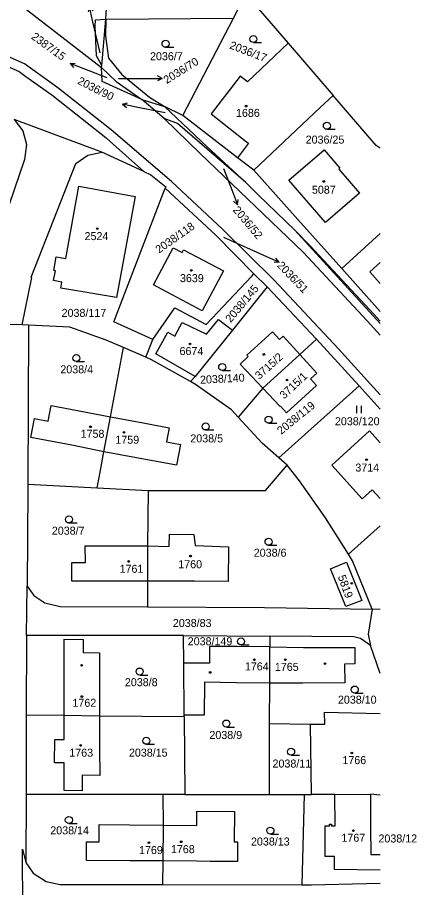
# Model space of a CAD drawing. Extents: x -667048 to -665920, y -1108425 to -1107247.
# Drawn here: x -666004.4 to -665919.6, y -1107911.7 to -1107726.9 of the extents above; entities that cross this region are included whole.
import ezdxf

# ---------------------------------------------------------------- set-up
doc = ezdxf.new("R2010")
doc.units = 0
for name, color, linetype in [('Default', 7, 'Continuous'), ('Hranice parcel', 7, 'Continuous'), ('Parcelní čísla', 7, 'Continuous'), ('Pop_ PČ_ popisy', 7, 'Continuous'), ('Značky budov', 7, 'Continuous'), ('Značky kultur', 7, 'Continuous')]:
    doc.layers.add(name, color=color, linetype=linetype)

# ---------------------------------------------------------------- blocks, each defined once
blk = doc.blocks.new('3.041')
at = {"layer": 'Default'}
blk.add_line((8, 0), (1758, 0), dxfattribs=at)
blk.add_circle((8, 750), 750, dxfattribs=at)
blk = doc.blocks.new('4.021')
at = {"layer": 'Default'}
blk.add_circle((-7, 1), 175, dxfattribs=at)
blk = doc.blocks.new('10291')
at = {"layer": 'Default'}
for p, q in [((0, 3001), (-500, 2001)), ((0, 1), (0, 3001)), ((0, 3001), (500, 2001))]:
    blk.add_line(p, q, dxfattribs=at)
blk = doc.blocks.new('3.061')
at = {"layer": 'Default'}
for p, q in [((-511, -1), (-511, 1499)), ((489, -1), (489, 1499))]:
    blk.add_line(p, q, dxfattribs=at)

msp = doc.modelspace()

# ---------------------------------------------------------------- linework, layer by layer
at = {"layer": 'Hranice parcel'}
for points in [[(-665985.61, -1107727.21), (-665985.17, -1107720.14)], [(-665958.54, -1107727.02), (-665955.87, -1107721.88)], [(-665955.87, -1107721.88), (-665946.87, -1107732.34)], [(-666004.06, -1107724), (-665986.55, -1107737.54)], [(-666025.82, -1107726.88), (-666018.01, -1107732.17), (-666004.04, -1107738.39)], [(-665987.87, -1107728.74), (-665987.84, -1107727.35), (-665985.61, -1107727.21)], [(-665986.51, -1107737.08), (-665985.61, -1107727.21)], [(-665985.61, -1107727.21), (-665985.72, -1107730.82), (-665985.06, -1107735.53), (-665982.21, -1107738.96), (-665976.38, -1107743.84)], [(-665985.61, -1107727.21), (-665958.54, -1107727.02)], [(-665969.29, -1107747.69), (-665958.54, -1107727.02)], [(-665987.64, -1107735), (-665987.87, -1107728.74)], [(-665927.32, -1107807.05), (-665936.22, -1107797.25), (-665949.88, -1107782.67), (-665960.81, -1107771.82), (-665971.71, -1107761.69), (-665984.47, -1107750.77), (-665995.85, -1107741.81), (-666002.94, -1107736.71), (-666017.32, -1107730.34)], [(-665946.87, -1107732.34), (-665955.55, -1107740.57), (-665957.08, -1107739.36), (-665963.26, -1107747.35), (-665955.73, -1107753.31), (-665955.35, -1107753.61), (-665957.62, -1107756.67)], [(-665946.87, -1107732.34), (-665937.35, -1107743.42)], [(-665986.51, -1107737.08), (-665987.64, -1107735)], [(-665986.55, -1107737.54), (-665986.51, -1107737.08)], [(-666004.04, -1107738.39), (-666002.62, -1107739.4), (-665997.13, -1107743.32)], [(-665986.55, -1107737.54), (-665983.44, -1107740.5)], [(-665986.44, -1107740.46), (-665986.55, -1107737.54)], [(-665977.97, -1107744.27), (-665986.44, -1107740.46)], [(-665983.44, -1107740.5), (-665977.97, -1107744.27)], [(-665997.13, -1107743.32), (-665985.59, -1107752.46)], [(-665977.97, -1107744.27), (-665973.15, -1107745.82)], [(-665973.21, -1107748.36), (-665977.97, -1107744.27)], [(-665976.38, -1107743.84), (-665973.15, -1107745.82)], [(-665937.35, -1107743.42), (-665940.06, -1107745.99), (-665954.17, -1107759.33)], [(-665927.32, -1107754.65), (-665928.17, -1107754.07), (-665937.35, -1107743.42)], [(-665973.15, -1107745.82), (-665964.12, -1107754.36), (-665955.88, -1107761.95)], [(-665969.29, -1107747.69), (-665973.15, -1107745.82)], [(-666005.07, -1107748.54), (-666003.24, -1107750.99), (-666002.46, -1107753.88), (-666002.9, -1107757.03), (-666007.26, -1107769.91)], [(-665986.51, -1107755.5), (-666005.07, -1107748.54)], [(-665955.88, -1107761.95), (-665970.4, -1107749.41), (-665973.21, -1107748.36)], [(-665973.21, -1107748.36), (-665965.59, -1107755.78)], [(-665957.62, -1107756.67), (-665969.29, -1107747.69)], [(-665985.59, -1107752.46), (-665984.69, -1107753.2), (-665977.55, -1107759.63)], [(-666001.49, -1107782.06), (-665992.01, -1107757.88), (-665989.42, -1107756.16), (-665986.51, -1107755.5)], [(-665977.55, -1107759.63), (-665986.51, -1107755.5)], [(-665965.59, -1107755.78), (-665943.74, -1107776.75), (-665930.08, -1107791.32), (-665927.32, -1107794.36)], [(-665936.13, -1107759.08), (-665931.75, -1107764.2), (-665938.99, -1107770.45), (-665946.72, -1107761.41), (-665939.25, -1107754.96), (-665935.9, -1107758.88), (-665936.13, -1107759.08)], [(-665954.17, -1107759.33), (-665957.62, -1107756.67)], [(-665977.55, -1107759.63), (-665976.1, -1107760.3), (-665972.87, -1107762.85), (-665973.01, -1107763.17)], [(-665954.17, -1107759.33), (-665944.84, -1107769.76), (-665935.5, -1107780.19)], [(-665996.16, -1107777.69), (-665994.1, -1107778.1), (-665991.36, -1107762.7), (-665979.43, -1107764.92), (-665983.34, -1107786.35), (-665995.2, -1107784.34), (-665994.98, -1107783.1), (-665996.72, -1107782.74)], [(-665975.67, -1107795.31), (-665983.9, -1107791.55), (-665973.01, -1107763.17)], [(-665973.01, -1107763.17), (-665962.21, -1107773.18), (-665954.19, -1107781.35)], [(-665953.27, -1107764.54), (-665955.88, -1107761.95)], [(-665945.48, -1107772.07), (-665953.27, -1107764.54)], [(-665945.48, -1107772.07), (-665942.27, -1107775.33), (-665928.65, -1107789.95), (-665927.32, -1107791.41)], [(-665927.32, -1107791.87), (-665945.48, -1107772.07)], [(-665935.5, -1107780.19), (-665927.32, -1107772.73)], [(-665975.49, -1107783.7), (-665971.29, -1107775.82), (-665969.44, -1107776.8), (-665969.12, -1107776.21)], [(-665969.12, -1107776.21), (-665960.63, -1107780.67), (-665965.16, -1107789.21), (-665973.69, -1107784.66), (-665975.49, -1107783.7)], [(-665996.72, -1107782.74), (-665996.34, -1107780.69), (-665996.66, -1107780.63), (-665996.16, -1107777.69)], [(-665927.32, -1107783.35), (-665929.51, -1107780.87), (-665927.32, -1107778.9)], [(-665975.67, -1107795.31), (-665970.99, -1107788.53), (-665964.34, -1107792.1), (-665954.63, -1107781.8), (-665954.19, -1107781.35)], [(-665954.19, -1107781.35), (-665951.33, -1107784.08)], [(-665935.5, -1107780.19), (-665927.32, -1107789.34)], [(-666003.37, -1107792.16), (-666001.33, -1107782.09), (-666001.49, -1107782.06)], [(-665951.33, -1107784.08), (-665958.74, -1107793.32)], [(-665951.33, -1107784.08), (-665940.85, -1107795.19)], [(-665966.63, -1107803.13), (-665975.02, -1107798.33), (-665972.45, -1107793.74), (-665970.96, -1107794.58), (-665969.38, -1107791.65), (-665965.88, -1107793.37), (-665964.26, -1107794.16), (-665961.69, -1107791.02), (-665958.74, -1107793.32)], [(-666003.37, -1107792.16), (-666009.37, -1107792.09)], [(-666002.02, -1107792.22), (-666003.37, -1107792.16)], [(-666002.02, -1107792.22), (-666002.02, -1107792.54), (-666002.2, -1107825.97)], [(-665993.27, -1107792.63), (-666002.02, -1107792.22)], [(-665981.88, -1107796.99), (-665985.59, -1107795.39), (-665993.27, -1107792.63)], [(-665958.74, -1107793.32), (-665966.63, -1107803.13)], [(-665952.28, -1107805.62), (-665955.87, -1107801.79), (-665957.1, -1107800.48), (-665955.42, -1107798.9), (-665955.68, -1107798.62), (-665950.2, -1107793.64), (-665948.72, -1107795.27), (-665947.96, -1107794.57), (-665944.39, -1107798.49)], [(-665977.16, -1107799.04), (-665975.67, -1107795.31)], [(-665940.85, -1107795.19), (-665944.39, -1107798.49)], [(-665940.85, -1107795.19), (-665931.8, -1107805.15)], [(-665984.61, -1107811.68), (-665981.88, -1107796.99)], [(-665977.16, -1107799.04), (-665981.88, -1107796.99)], [(-665944.39, -1107798.49), (-665940.81, -1107802.41), (-665942.14, -1107803.62), (-665940.86, -1107805.03), (-665947.26, -1107810.86), (-665948.54, -1107809.46), (-665948.61, -1107809.53), (-665952.28, -1107805.62)], [(-665944.39, -1107798.49), (-665952.28, -1107805.62)], [(-665967.66, -1107804.21), (-665975.93, -1107799.57), (-665977.16, -1107799.04)], [(-665966.63, -1107803.13), (-665967.66, -1107804.21)], [(-665958.94, -1107810.23), (-665966.57, -1107804.82), (-665967.66, -1107804.21)], [(-665952.28, -1107805.62), (-665957.54, -1107811.75)], [(-665948.85, -1107820.43), (-665931.8, -1107805.15)], [(-665931.8, -1107805.15), (-665927.32, -1107810.04)], [(-665992.88, -1107817.72), (-666001.54, -1107816.06), (-666000.81, -1107812.02), (-665997.86, -1107812.6), (-665997.26, -1107809.31), (-665991.62, -1107810.34)], [(-665991.62, -1107810.34), (-665984.61, -1107811.68)], [(-665957.54, -1107811.75), (-665958.94, -1107810.23)], [(-665986.03, -1107819.11), (-665984.61, -1107811.68)], [(-665984.61, -1107811.68), (-665977.69, -1107813)], [(-665977.69, -1107813), (-665972.17, -1107814.05), (-665972.74, -1107817.01), (-665969.79, -1107817.57), (-665970.63, -1107822), (-665979.11, -1107820.42)], [(-665952.4, -1107817.31), (-665957.54, -1107811.75)], [(-665927.32, -1107817.21), (-665929.62, -1107814.68), (-665937.64, -1107821.99), (-665931.14, -1107829.12), (-665929.03, -1107827.2), (-665927.35, -1107829.05), (-665927.32, -1107829.02)], [(-665986.03, -1107819.11), (-665992.88, -1107817.72)], [(-665948.85, -1107820.43), (-665952.4, -1107817.31)], [(-665986.84, -1107823.44), (-665986.03, -1107819.11)], [(-665979.11, -1107820.42), (-665986.03, -1107819.11)], [(-665947.13, -1107821.95), (-665948.85, -1107820.43)], [(-665976.6, -1107827.34), (-665951.71, -1107827.35), (-665947.13, -1107821.95)], [(-665934.06, -1107840.9), (-665938.98, -1107833.13), (-665944.45, -1107825.26), (-665947.13, -1107821.95)], [(-665987.46, -1107826.76), (-665986.84, -1107823.44)], [(-666002.2, -1107825.97), (-666002.21, -1107826.93), (-666002.33, -1107847.65)], [(-666002.2, -1107825.97), (-665987.46, -1107826.76)], [(-665987.46, -1107826.76), (-665976.6, -1107827.34)], [(-665976.6, -1107827.34), (-665976.77, -1107839.07)], [(-665934.06, -1107840.9), (-665927.32, -1107834.83)], [(-665976.77, -1107839.07), (-665972.17, -1107839.22), (-665972.09, -1107836.65)], [(-665972.09, -1107836.65), (-665966.95, -1107836.67), (-665966.63, -1107839.05), (-665959.59, -1107839.31), (-665959.61, -1107846.7), (-665966.77, -1107846.6), (-665969.69, -1107846.6), (-665976.76, -1107846.61)], [(-665983.83, -1107846.61), (-665992.83, -1107846.6), (-665992.84, -1107842.65), (-665989.98, -1107842.65), (-665989.99, -1107839.08), (-665983.84, -1107839.08)], [(-665983.84, -1107839.08), (-665976.77, -1107839.07)], [(-665976.77, -1107839.07), (-665976.76, -1107846.61)], [(-665929.04, -1107852.52), (-665933.2, -1107842.26), (-665934.06, -1107840.9)], [(-665937.88, -1107843.97), (-665934.47, -1107842.6), (-665931.23, -1107850.72), (-665934.64, -1107851.99), (-665937.88, -1107843.97)], [(-666002.47, -1107858.11), (-666002.33, -1107847.65)], [(-666002.33, -1107847.65), (-666000.9, -1107849.62), (-665998.61, -1107851.2), (-665995.3, -1107851.98)], [(-665976.76, -1107846.61), (-665983.83, -1107846.61)], [(-665976.76, -1107846.61), (-665976.81, -1107852.09)], [(-665995.3, -1107851.98), (-665976.81, -1107852.09)], [(-665976.81, -1107852.09), (-665951.91, -1107852.23), (-665929.04, -1107852.52)], [(-665929.04, -1107852.52), (-665929.89, -1107857.87), (-665929.4, -1107860.3)], [(-665927.32, -1107852.59), (-665929.04, -1107852.52)], [(-666002.47, -1107858.11), (-666002.52, -1107875.01)], [(-665969.12, -1107858.14), (-666002.47, -1107858.11)], [(-665994.49, -1107867.93), (-665994.47, -1107858.91), (-665990.42, -1107858.97), (-665990.42, -1107861.74), (-665986.98, -1107861.79), (-665986.99, -1107868.03)], [(-665969.07, -1107864.02), (-665969.12, -1107858.14)], [(-665969.12, -1107858.14), (-665950.79, -1107858.32)], [(-665950.79, -1107858.32), (-665950.8, -1107860.58)], [(-665929.4, -1107860.3), (-665931.54, -1107858.75), (-665932.97, -1107858.44), (-665950.79, -1107858.32)], [(-665950.8, -1107860.58), (-665957.8, -1107860.47), (-665963.58, -1107860.51), (-665963.63, -1107864), (-665966.8, -1107864.01), (-665969.07, -1107864.02)], [(-665950.82, -1107868.29), (-665950.8, -1107860.58)], [(-665950.8, -1107860.58), (-665943.63, -1107860.7), (-665932.74, -1107860.66), (-665932.7, -1107864.19), (-665934.93, -1107864.2), (-665934.88, -1107868.22), (-665943.76, -1107868.25)], [(-665927.32, -1107866.2), (-665929.4, -1107860.3)], [(-665968.97, -1107875.08), (-665969.07, -1107864.02)], [(-665994.49, -1107875.09), (-665994.49, -1107867.93)], [(-665986.99, -1107868.03), (-665986.96, -1107875.17)], [(-665950.82, -1107868.29), (-665957.87, -1107868.17), (-665964.68, -1107868.03), (-665964.73, -1107875.06)], [(-665950.84, -1107876.8), (-665950.82, -1107868.29)], [(-665943.76, -1107868.25), (-665950.82, -1107868.29)], [(-666002.52, -1107875.01), (-666002.58, -1107891.93)], [(-666002.52, -1107875.01), (-665994.49, -1107875.09)], [(-665986.94, -1107882.17), (-665986.9, -1107887.88), (-665990.62, -1107887.84), (-665990.63, -1107891.12), (-665994.51, -1107891.07), (-665994.49, -1107885.2), (-665996.51, -1107885.2), (-665996.47, -1107880.24), (-665994.5, -1107880.2), (-665994.49, -1107875.09)], [(-665994.49, -1107875.09), (-665986.96, -1107875.17)], [(-665986.96, -1107875.17), (-665986.94, -1107882.17)], [(-665986.96, -1107875.17), (-665968.97, -1107875.37)], [(-665964.73, -1107875.06), (-665968.97, -1107875.08)], [(-665968.97, -1107875.37), (-665968.97, -1107875.08)], [(-665968.97, -1107875.37), (-665968.83, -1107891.91)], [(-665942.12, -1107876.95), (-665939.11, -1107876.96), (-665939.15, -1107874.44), (-665927.32, -1107874.74)], [(-665950.88, -1107891.89), (-665950.84, -1107876.8)], [(-665950.84, -1107876.8), (-665942.12, -1107876.95)], [(-665941.96, -1107891.88), (-665942.12, -1107876.95)], [(-666002.58, -1107891.93), (-666002.62, -1107906.32)], [(-665973.53, -1107891.94), (-666002.58, -1107891.93)], [(-665968.83, -1107891.91), (-665973.53, -1107891.94)], [(-665973.53, -1107891.94), (-665973.46, -1107898.42)], [(-665968.83, -1107891.91), (-665950.88, -1107891.89)], [(-665950.88, -1107891.89), (-665943.5, -1107891.89)], [(-665943.5, -1107891.89), (-665943.96, -1107911.08)], [(-665943.5, -1107891.89), (-665941.96, -1107891.88)], [(-665936.95, -1107891.88), (-665941.96, -1107891.88)], [(-665927.32, -1107907.95), (-665937.06, -1107907.83), (-665937.03, -1107905.1), (-665939.01, -1107905.1), (-665939.05, -1107898.59), (-665938.07, -1107898.59), (-665938.08, -1107898.23), (-665937.72, -1107898.23), (-665937.72, -1107898.59), (-665936.94, -1107898.6), (-665936.95, -1107891.88)], [(-665936.95, -1107891.88), (-665929.38, -1107891.87)], [(-665929.38, -1107891.87), (-665929.39, -1107898.91)], [(-665927.32, -1107892.08), (-665929.38, -1107891.87)], [(-665973.46, -1107898.42), (-665966.32, -1107898.48), (-665966.3, -1107895.48), (-665958.32, -1107895.54)], [(-665958.32, -1107895.54), (-665958.37, -1107901.94), (-665957.65, -1107901.95), (-665957.68, -1107906.14), (-665958.4, -1107906.15)], [(-665980.52, -1107905.98), (-665989.73, -1107905.91), (-665989.74, -1107901.94), (-665987.05, -1107901.96), (-665987.06, -1107898.27), (-665980.53, -1107898.36)], [(-665980.53, -1107898.36), (-665973.46, -1107898.42)], [(-665973.46, -1107898.42), (-665973.52, -1107906.03)], [(-665929.39, -1107898.91), (-665929.36, -1107904.69), (-665927.32, -1107904.66)], [(-666002.18, -1107916.98), (-666003.25, -1107916.98), (-666003.34, -1107903.53), (-666002.62, -1107906.32)], [(-666002.62, -1107906.32), (-666001.06, -1107908.59), (-665998.29, -1107910.4), (-665995.33, -1107911)], [(-665973.52, -1107906.03), (-665980.52, -1107905.98)], [(-665973.52, -1107906.03), (-665973.56, -1107911.03)], [(-665958.4, -1107906.15), (-665963.47, -1107906.11), (-665966.4, -1107906.09), (-665973.52, -1107906.03)], [(-665995.33, -1107911), (-665973.56, -1107911.03)], [(-665973.56, -1107911.03), (-665943.96, -1107911.08)], [(-665943.96, -1107911.08), (-665942.02, -1107911.08), (-665927.32, -1107910.75)]]:
    msp.add_lwpolyline(points, dxfattribs=at)
at = {"layer": 'Pop_ PČ_ popisy'}
for points in [[(-665986.84, -1107734.39), (-665988.45, -1107727.51)], [(-665985.37, -1107739.71), (-665990.43, -1107737.75)], [(-665982.91, -1107739.86), (-665976.63, -1107739.81)], [(-665973.05, -1107747.1), (-665979.17, -1107745.9)], [(-665960.62, -1107758.93), (-665958.73, -1107763.85)], [(-665960.62, -1107773.55), (-665951.52, -1107777.63)]]:
    msp.add_lwpolyline(points, dxfattribs=at)

# ---------------------------------------------------------------- block references
for p, xscale, yscale, rotation in [((-665988.45, -1107727.51), 0.0010000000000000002, 0.0010000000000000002, 13.000000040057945), ((-665990.43, -1107737.75), 0.001, 0.0010000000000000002, 69.00000000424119), ((-665976.63, -1107739.81), 0.0010000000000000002, 0.0010000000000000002, -90.00000000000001), ((-665979.17, -1107745.9), 0.0010000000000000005, 0.0010000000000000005, 79.00000005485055), ((-665958.73, -1107763.85), 0.0010000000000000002, 0.0010000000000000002, -159.0000000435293), ((-665951.52, -1107777.63), 0.001, 0.0010000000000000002, -114.00000005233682)]:
    msp.add_blockref('10291', p, dxfattribs=dict(at, xscale=xscale, yscale=yscale, rotation=rotation))
at = {"layer": 'Značky budov', "xscale": 0.0010000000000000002, "yscale": 0.0010000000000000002}
for p in [(-665955.82, -1107745.71), (-665939.32, -1107761.71), (-665987.44, -1107771.72), (-665967.46, -1107780.62), (-665967.73, -1107796.22), (-665952.04, -1107798.45), (-665947.12, -1107803.89), (-665988.88, -1107813.81), (-665981.75, -1107815), (-665930.23, -1107820.79), (-665980.76, -1107842.42), (-665967.62, -1107841.29), (-665933.38, -1107847.05), (-665954.06, -1107863.3), (-665947.49, -1107863.3), (-665990.77, -1107864.48), (-665939.05, -1107864.11), (-665963.45, -1107865.99), (-665990.71, -1107871.11), (-665990.96, -1107881.5), (-665933.36, -1107883.11), (-665933.03, -1107899.59), (-665976.48, -1107902.15), (-665969.6, -1107901.96)]:
    msp.add_blockref('4.021', p, dxfattribs=at)
at = {"layer": 'Značky kultur', "xscale": 0.0010000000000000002, "yscale": 0.0010000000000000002}
for name, p in [('3.041', (-665972.95, -1107733.22)), ('3.041', (-665954.29, -1107732.22)), ('3.041', (-665938.67, -1107750.63)), ('3.041', (-665991.91, -1107799.97)), ('3.041', (-665960.91, -1107801.88)), ('3.061', (-665931.79, -1107810.89)), ('3.041', (-665964.43, -1107814.49)), ('3.041', (-665951.07, -1107813.06)), ('3.041', (-665993.47, -1107834.24)), ('3.041', (-665951.06, -1107838.99)), ('3.041', (-665956.91, -1107860.15)), ('3.041', (-665978.44, -1107866.55)), ('3.041', (-665932.75, -1107870.38)), ('3.041', (-665960.03, -1107877.59)), ('3.041', (-665977.02, -1107881.25)), ('3.041', (-665946.27, -1107883.58)), ('3.041', (-665993.49, -1107898.08)), ('3.041', (-665950.67, -1107900.33))]:
    msp.add_blockref(name, p, dxfattribs=at)

# ---------------------------------------------------------------- texts
at = {"layer": 'Parcelní čísla'}
for s, rotation, p in [('2387/15', 324, (-666001.6, -1107731.29)), ('2036/17', 339, (-665959.49, -1107733.42)), ('2036/70', 32, (-665972.7, -1107741.05)), ('2036/90', 333, (-665991.8, -1107740.89)), ('2036/52', 310, (-665958.74, -1107767.83)), ('2038/118', 35, (-665974.34, -1107777.07)), ('2036/51', 314, (-665949.37, -1107779.67)), ('2038/145', 50, (-665959.11, -1107791.81)), ('3715/2', 42, (-665953.01, -1107803.87)), ('2038/140', 3, (-665965.57, -1107804.69)), ('3715/1', 43, (-665947.74, -1107808.02)), ('2038/119', 39, (-665948.38, -1107815.55)), ('5819', 290, (-665936.38, -1107845.64))]:
    msp.add_text(s, height=1.7, rotation=rotation, dxfattribs=at).set_placement(p)
for s, p in [('2036/7', (-665976.24, -1107735.96)), ('1686', (-665957.98, -1107748)), ('2036/25', (-665943.17, -1107753.67)), ('5087', (-665941.84, -1107764.32)), ('2524', (-665990.15, -1107774.17)), ('3639', (-665969.88, -1107783.09)), ('2038/117', (-665995.02, -1107790.47)), ('6674', (-665969.97, -1107798.58)), ('2038/4', (-665995.29, -1107802.46)), ('2038/120', (-665936.96, -1107813.49)), ('1758', (-665990.98, -1107816.15)), ('1759', (-665983.6, -1107817.41)), ('2038/5', (-665967.68, -1107817.13)), ('3714', (-665932.62, -1107823.33)), ('2038/7', (-665997.1, -1107836.73)), ('2038/6', (-665954.2, -1107841.41)), ('1760', (-665970.24, -1107843.86)), ('1761', (-665982.71, -1107844.83)), ('2038/83', (-665971.39, -1107856.33)), ('2038/149', (-665968.23, -1107860.22)), ('1764', (-665956.09, -1107865.56)), ('1765', (-665949.72, -1107865.65)), ('2038/8', (-665981.58, -1107868.91)), ('1762', (-665992.72, -1107873.29)), ('2038/10', (-665936.32, -1107872.62)), ('2038/9', (-665963.62, -1107880.12)), ('1763', (-665993.39, -1107883.88)), ('2038/15', (-665980.72, -1107883.87)), ('2038/11', (-665950.21, -1107886.19)), ('1766', (-665935.37, -1107885.46)), ('2038/14', (-665997.43, -1107900.38)), ('2038/13', (-665954.79, -1107902.75)), ('1767', (-665935.58, -1107901.95)), ('2038/12', (-665927.71, -1107902.1)), ('1769', (-665978.58, -1107904.56)), ('1768', (-665971.8, -1107904.37))]:
    msp.add_text(s, height=1.7, dxfattribs=at).set_placement(p)

doc.saveas('drawing.dxf')
